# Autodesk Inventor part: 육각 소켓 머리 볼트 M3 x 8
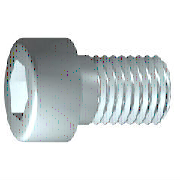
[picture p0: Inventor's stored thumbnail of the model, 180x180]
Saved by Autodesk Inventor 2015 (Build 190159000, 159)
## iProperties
Created: 2012-02
Part Number: 육각 소켓 머리 볼트 M3 x 8
Material: 강철, 연강
Description: 6각 소켓 머리 캡 나사
Document SubType Name: Modeling
Standard: ISO 4762
Designer: mdu-01
Standard Revision: Fourth edition 2004-03-01
Standards Organization: ISO
Language: ko-KR
Size Designation: M3 x 8
Categories: <MemberInstance><Categories><Category DisplayName="조임쇠" InternalName="e4da775c-781d-43d5-af7c-5136215cf5a6" Mnemonic="FSTN"><Category DisplayName="볼트" InternalN
Density: 7.75 g/cm^3
Appearance: 강철
IsCustomPart: 1
Author: mdu-01
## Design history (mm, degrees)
sketch "스케치1"
  geometry: L1 (-0.867, 0)-(8, 0); L2 (8, 0)-(8, 1.5); L3 (8, 1.5)-(1.25, 1.5); L4 (1.25, 1.5)-(0.943, 1.5); L5 (0.943, 1.5)-(0, 1.5); L6 (0, 1.5)-(0, 2.75); L7 (0, 2.75)-(-3, 2.75); L8 (-3, 2.75)-(-3, 1.443); L9 (-3, 1.443)-(-1.7, 1.443); L10 (-1.7, 1.443)-(-0.867, 0); L11 (-5.2, 0)-(10.2, 0) reference; L12 (0, -0.55)-(0, 3.3) reference; L13 (1.25, 1.5)-(0, 1.5)
  constraints: 22 end point, 6 parallel, 2 collinear, 2 perpendicular, 1 horizontal, 1 point on line
  dimensions: "d1" = 6.75 distance from line of L3.end L2 (= GEL); "d2" = 0.30683 distance of L4.end L3.end (computed from GAL); "d3" = 3 distance between parallel lines of L8 L6 (= KOH); "d4" = 1.3 distance of L8.end L9.end (= INTI); "d5" = 60 deg angle of L10 L1; "d6" = 3 diameter of L3 L1 (= GD); "d7" = 3 diameter of L5 L1 (= BDM); "d8" = 2.88675 diameter of L9 L1 (= 1.1547 x SW); "d9" = 5.5 diameter of L7 L1 (= KOD); "d26" = 8 distance between parallel lines of L12 L2 (= NLG)
revolve "본체" sketch "스케치1" stored, may be unused: angle "d10" = 90 deg
sketch "스케치2"
  geometry: L1 (0, -3.85)-(0, 3.85) reference; L2 (-3.85, 0)-(3.85, 0) reference; L3 (1.443, 0)-(0.722, -1.25); L4 (0.722, -1.25)-(-0.722, -1.25); L5 (-0.722, -1.25)-(-1.443, 0); L6 (-1.443, 0)-(-0.722, 1.25); L7 (-0.722, 1.25)-(0.722, 1.25); L8 (0.722, 1.25)-(1.443, 0); 2 further points
  constraints: 12 end point, 1 coincident, 1 horizontal alignment, 1 point on line, 12 other
extrude "슬롯" join sketch "스케치2" stored distance "d11" = 10; taper "d12" = 0 deg
workplane "Work Plane1"
fillet "Fillet2" dims "d30" = 0.1 (= R)
body "Solid1"
fillet "모깎기1" dims "d17" = 0.3 (= RR)
feature "스레드" dims "d13" = 6.75 (= GEL), "d14" = 0
chamfer "모따기1" distance "d15" = 0.30673 (= -0.5 x SPD + 0.5 x GD); stored, may be unused: second distance "d16" = 0.30673 (= GUL), angle "d27" = 45 deg
other parameters: "GD" = 3 [user parameter; used in 2 equation terms], "NLG" = 8 [user parameter; used in 1 equation term], "GEL" = 6.75 [user parameter; used in 2 equation terms], "KOD" = 5.5 [user parameter; used in 1 equation term], "KOH" = 3 [user parameter; used in 1 equation term], "INTI" = 1.3 [user parameter; used in 1 equation term], "GAL" = 0.30673 (= 0.61345 x PTC) [user parameter; used in 1 equation term], "GUL" = 0.30673 (= 0.61345 x PTC) [user parameter; used in 1 equation term], "BDM" = 3 (= NND) [user parameter; used in 1 equation term], "SW" = 2.5 [user parameter; used in 2 equation terms], "RR" = 0.3 [user parameter; used in 1 equation term], "SPD" = 2.38655 (= NND - 1.2269 x PTC) [user parameter; used in 1 equation term], "d19" = 0, "d28" = 0, "d29" = 0, "R" = 0.1 [user parameter; used in 1 equation term], "TOA" = 30 deg [user parameter], "GD1" = 2.38655 (= THREADDIA - 1.2269 x PTC) [user parameter], "THREADDIA" = 3 [user parameter; used in 1 equation term], "FAWI" = 45 deg [user parameter], "PTC" = 0.5 [user parameter; used in 5 equation terms], "NND" = 3 [user parameter; used in 2 equation terms], "E0" = 2.8875 (= 1.155 x SW) [user parameter]
